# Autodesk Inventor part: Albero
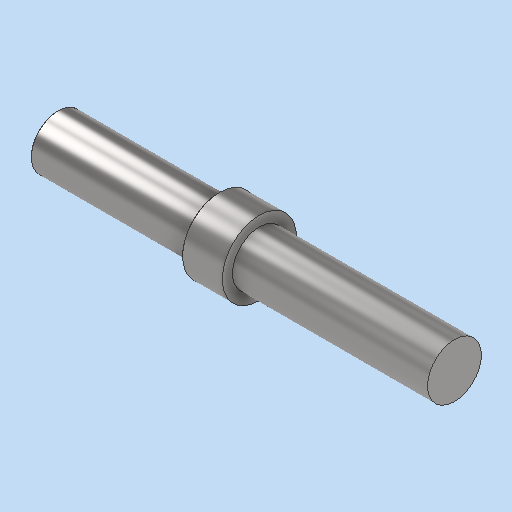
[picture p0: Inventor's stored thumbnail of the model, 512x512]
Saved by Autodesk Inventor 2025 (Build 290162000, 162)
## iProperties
CustomPartVersion: 1
Created: 2026-05
Part Number: Albero
Material: Steel
Document SubType Name: Modeling
Designer: R5800u
Density: 1 g/cm^3
Appearance: Semilucidato
Length: 295,000 mm
Author: R5800u
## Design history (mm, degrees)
sketch "Schizzo principale"
  geometry: L1 (0, 0)-(295, 0) reference; L2 (0, 0)-(0, 20); L3 (0, 20)-(120, 20); L4 (120, 20)-(120, 27.5); L5 (120, 27.5)-(150, 27.5); L6 (295, 20)-(295, 0); L7 (150, 20)-(295, 20); L8 (150, 27.5)-(150, 20)
  constraints: 16 end point, 4 vertical, 2 horizontal
  dimensions: "d3" = 40 diameter of L3 L1 (derived); "d4" = 55 diameter of L5 L1 (derived); "d5" = 40 diameter of L7 L1 (derived)
revolve "Rivoluzione1" sketch "Schizzo principale" stored, may be unused: angle "d6" = 0 deg
chamfer "Smusso4" distance "d18" = 0.5; stored, may be unused: second distance "d19" = 0.125, angle "d20" = 45 deg
chamfer "Smusso1" distance "d7" = 0.5; stored, may be unused: second distance "d8" = 0.125, angle "d9" = 45 deg
chamfer "Smusso2" distance "d11" = 0.5; stored, may be unused: second distance "d12" = 0.125, angle "d13" = 45 deg
node "Scanalatura2"
node "Scanalatura3"
node "Solido1"
feature "Sede per chiavetta albero"
feature "Sede per chiavetta albero2"
other parameters: "d0" = 0, "d1" = 0, "d2" = 0, "Length" = 295 [user parameter]
